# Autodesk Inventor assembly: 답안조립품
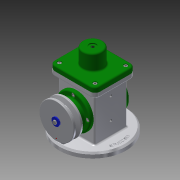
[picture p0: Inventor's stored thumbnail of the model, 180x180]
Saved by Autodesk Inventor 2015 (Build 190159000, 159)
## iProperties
Created: 2019-08
Part Number: 답안조립품
Document SubType Name: Assembly
Designer: now
Author: now
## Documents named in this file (18)
- C:\Users\now\Desktop\490804V1030\답안조립품.iam
- C:\Users\now\Desktop\490804V1030\E-링.ipt
- C:\Users\now\Desktop\490804V1030\V-벨트풀리.ipt
- C:\Users\now\Desktop\490804V1030\덮개.ipt
- C:\Users\now\Desktop\490804V1030\뒤커버.ipt
- C:\Users\now\Desktop\490804V1030\링크.ipt
- C:\Users\now\Desktop\490804V1030\베어링 17 x 40 x 12.ipt
- C:\Users\now\Desktop\490804V1030\본체.ipt
- C:\Users\now\Desktop\490804V1030\볼트 M4 x 8.ipt
- C:\Users\now\Desktop\490804V1030\볼트 M4 x 10.ipt
- C:\Users\now\Desktop\490804V1030\슬라이더.ipt
- C:\Users\now\Desktop\490804V1030\앞커버.ipt
- C:\Users\now\Desktop\490804V1030\오일 실 17 30 8.ipt
- C:\Users\now\Desktop\490804V1030\와셔 4x16.ipt
- C:\Users\now\Desktop\490804V1030\클레비스 핀 6 x 22.ipt
- 클레비스 핀 6 x 22.ipt
- C:\Users\now\Desktop\490804V1030\키 4 x 4 x 12.ipt
- C:\Users\now\Desktop\490804V1030\편심축.ipt
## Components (2 placed, 2 different names)
1. E-링:1
2. V-벨트풀리:1 — 각도:2
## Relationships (1: Angle 1)
- 각도:2 [Angle]: V-벨트풀리:1
